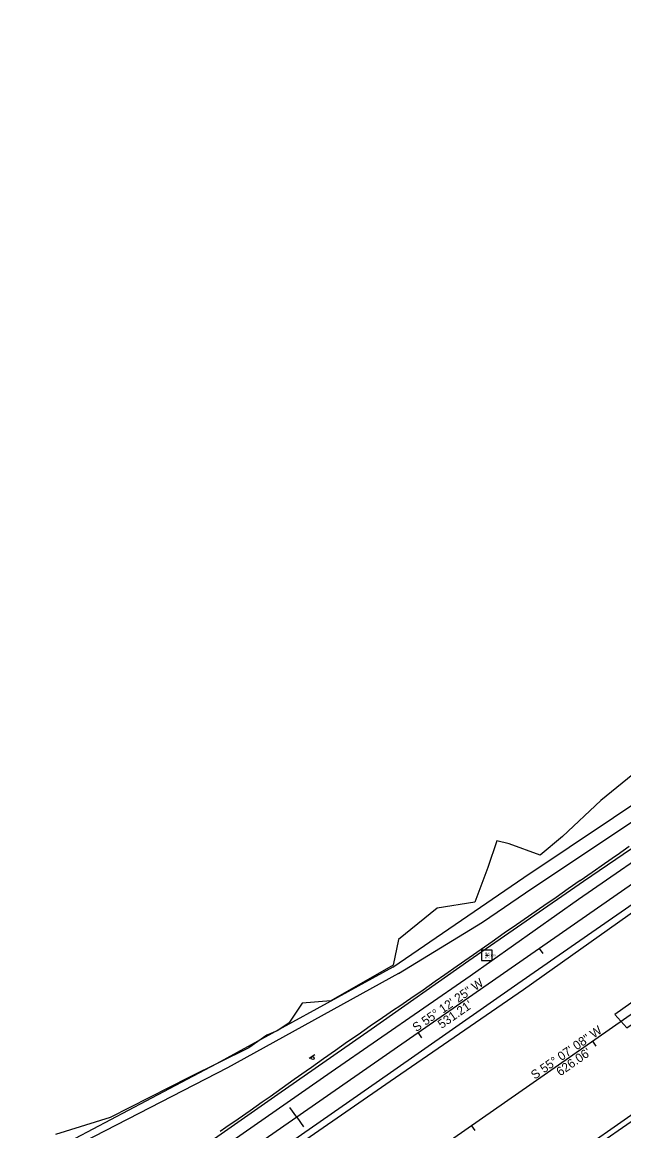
# Model space of a CAD drawing. Extents: x 1901471 to 1963503, y 756461 to 799997.
# Drawn here: x 1902497 to 1902904, y 757432 to 758182 of the extents above; entities that cross this region are included whole.
import ezdxf

# ---------------------------------------------------------------- set-up
doc = ezdxf.new("R2010")
doc.units = 0
for name, color, linetype in [('RD_DTM_BkLn1', 7, 'Continuous'), ('RD_EX_Bldg', 7, 'Continuous'), ('RD_EX_BldgApp', 7, 'Continuous'), ('RD_EX_DR_ErosCtrl', 7, 'Continuous'), ('RD_EX_Road', 7, 'Continuous'), ('RD_EX_Road_txCode', 7, 'Continuous'), ('RD_EX_VEG', 7, 'Continuous'), ('RD_HC_Cl', 7, 'Continuous'), ('RD_HC_Data', 7, 'Continuous'), ('RD_HC_Data_Tic', 7, 'Continuous'), ('RD_HC_Survey', 7, 'Continuous'), ('RD_HC_txCode', 7, 'Continuous'), ('RD_SMD_Locator', 7, 'Continuous')]:
    doc.layers.add(name, color=color, linetype=linetype)

# ---------------------------------------------------------------- blocks, each defined once
blk = doc.blocks.new('SIGN')
at = {"layer": 'RD_EX_BldgApp'}
blk.add_line((-4.5, -2), (4.5, -2), dxfattribs=at)
blk.add_circle((0, 0), 2, dxfattribs=at)

msp = doc.modelspace()

# ---------------------------------------------------------------- linework, layer by layer
at = {"layer": 'RD_DTM_BkLn1'}
for points in [[(1902874.32, 757601.2), (1902882.5, 757606.95), (1902890.67, 757612.7), (1902898.85, 757618.46), (1902899.21, 757618.71), (1902907.4, 757624.45)], [(1902874.32, 757601.2), (1902866.12, 757595.49), (1902857.91, 757589.79), (1902849.71, 757584.08), (1902841.51, 757578.37), (1902839.34, 757576.86), (1902831.13, 757571.17), (1902822.92, 757565.48), (1902814.71, 757559.79), (1902807.28, 757554.64), (1902799.11, 757548.89), (1902790.93, 757543.15), (1902782.76, 757537.4), (1902776.16, 757532.76), (1902767.92, 757527.1), (1902759.69, 757521.44), (1902751.46, 757515.78), (1902748.68, 757513.88), (1902740.46, 757508.21), (1902732.23, 757502.54), (1902724, 757496.87), (1902716.84, 757491.93), (1902708.68, 757486.17), (1902700.52, 757480.41), (1902692.37, 757474.65), (1902688.88, 757472.19), (1902680.71, 757466.43), (1902672.55, 757460.66), (1902664.39, 757454.9), (1902659.04, 757451.13), (1902650.85, 757445.41), (1902642.66, 757439.69), (1902634.47, 757433.97), (1902630.55, 757431.23)]]:
    msp.add_lwpolyline(points, dxfattribs=at)
at = {"layer": 'RD_EX_DR_ErosCtrl'}
for points in [[(1902747.46, 757542.46), (1902836.19, 757603.28), (1902927.62, 757664.43), (1903019.85, 757727.82), (1903105.99, 757786.13), (1903203.25, 757851.35), (1903242.32, 757877.29), (1903298.99, 757915.31), (1903338.66, 757941.04), (1903399.27, 757980.01), (1903462.39, 758020.38), (1903504.9, 758047.93), (1903529.93, 758066.9), (1903582.19, 758100.04), (1903632.56, 758131.91), (1903684.35, 758164.03), (1903699.94, 758182.29)], [(1902751.25, 757538.29), (1902808.08, 757572.96), (1902842.29, 757596.37), (1902919.08, 757647.57), (1902952.01, 757670.16), (1902995.77, 757699.76), (1903030.25, 757723.21), (1903111.16, 757778.54), (1903204.19, 757840.96), (1903254.44, 757875.32), (1903318.2, 757916.49), (1903382.9, 757957.81), (1903452, 758001.97), (1903511.04, 758039.98), (1903531.19, 758048.88), (1903599.19, 758091.54), (1903664.68, 758132.54), (1903699.94, 758153.56), (1903712.69, 758175.05)], [(1902747.46, 757542.46), (1902628.19, 757477.23), (1902496.57, 757407.55)], [(1902751.25, 757538.29), (1902635.44, 757474.33), (1902500.2, 757404.65)]]:
    msp.add_lwpolyline(points, dxfattribs=at)
msp.add_lwpolyline([(1903199.35, 757720.63), (1903054.59, 757619.06), (1902954.08, 757550.41), (1902897.83, 757510.56), (1902905.83, 757501.49), (1903034.86, 757590.27), (1903129.23, 757656.25), (1903191.88, 757700.1), (1903199.88, 757705.7), (1903250.13, 757740.42), (1903304.34, 757776.7), (1903375.13, 757825.43), (1903438.82, 757866.9), (1903517.32, 757917.55), (1903583.67, 757959.61), (1903576.56, 757969.98), (1903544.57, 757950.73), (1903466.96, 757900.52), (1903399.72, 757856.98), (1903308.19, 757794.62)], close=True, dxfattribs=at)
at = {"layer": 'RD_EX_Road'}
for points in [[(1902544.26, 757369.41), (1902570.72, 757387.8), (1902622.18, 757423.49), (1902669.73, 757456.61), (1902732.72, 757500.69), (1902798.95, 757547.06), (1902876.59, 757600.87), (1902935.77, 757641.26), (1902978.73, 757671.24), (1903030.53, 757707.27), (1903089.15, 757747.99), (1903161.76, 757796.94), (1903199.46, 757822.28), (1903310.27, 757894.1), (1903405, 757954.73), (1903466.2, 757993.19), (1903543.88, 758041.32), (1903647.51, 758104.6), (1903717.43, 758146.66)], [(1902549.89, 757362.97), (1902608.83, 757404.26), (1902705.74, 757471.74), (1902799.73, 757536.65), (1902873.23, 757588.57), (1902936.5, 757632.27), (1902993.18, 757671.04), (1903109.1, 757751.12), (1903199.43, 757812.56), (1903258.13, 757850.9), (1903325.96, 757895.04), (1903389.06, 757935.18), (1903464.89, 757982.87), (1903523.83, 758019.15), (1903589, 758059.44), (1903665.72, 758105.79), (1903735.62, 758147.86)], [(1902568.41, 757341.74), (1902587.99, 757355.26), (1902664.42, 757409.2), (1902745.6, 757465.34), (1902835.93, 757527.5), (1902925.89, 757591.32), (1902994.27, 757639.22), (1903088.26, 757703.77), (1903147.87, 757743.81), (1903191.75, 757773.43), (1903200.16, 757779.65), (1903243.02, 757807.06), (1903304.64, 757847.2), (1903362.69, 757886.01), (1903465.18, 757951.02), (1903571.82, 758016.63), (1903672.83, 758077.8), (1903785.09, 758144.01)], [(1902565.36, 757345.24), (1902587.93, 757360.91), (1902678.13, 757424.09), (1902745.99, 757471.23), (1902832.13, 757531.57), (1902912.99, 757587.64), (1902992.63, 757642.29), (1903093.4, 757712.18), (1903200.26, 757784.5), (1903242.13, 757812.69), (1903303.45, 757852.68), (1903394.98, 757911.48), (1903474.66, 757961.39), (1903541.6, 758003.16), (1903638.76, 758062.84), (1903731.48, 758118.38)], [(1902642.69, 757256.64), (1902673.85, 757278.35), (1902740.23, 757324.07), (1902776.75, 757349.93), (1902855.4, 757405.11), (1902924.98, 757453.9), (1903008.95, 757512.15), (1903064.67, 757550.8), (1903124.84, 757592.59), (1903162.77, 757619.44), (1903199.56, 757645.18), (1903308.36, 757720.73), (1903405.55, 757786.65), (1903520.21, 757864.13), (1903629.25, 757935.1), (1903744.21, 758008.43)], [(1902645.38, 757253.55), (1902740.71, 757320.07), (1902853.67, 757399.92), (1902941.03, 757460.46), (1903022.29, 757516.73), (1903115.34, 757581.75), (1903177.91, 757624.61), (1903200.26, 757640.46), (1903294.43, 757705.62), (1903403.47, 757780.73), (1903463.92, 757821.32), (1903530.58, 757865.32), (1903625.69, 757927.99), (1903700.66, 757976.28), (1903748.66, 758006.65)]]:
    msp.add_lwpolyline(points, dxfattribs=at)
at = {"layer": 'RD_EX_VEG'}
msp.add_lwpolyline([(1902909.89, 757673), (1902888.32, 757655.45), (1902862.24, 757631.12), (1902847.11, 757618.34), (1902826.27, 757626.11), (1902817.75, 757628.19), (1902811.68, 757610), (1902803.04, 757586.47), (1902777.46, 757582.46), (1902751.38, 757561.39), (1902747.65, 757543.88), (1902705.58, 757519.82), (1902686.16, 757518.25), (1902677.13, 757504.7), (1902669.21, 757499.55), (1902662.08, 757496.43), (1902650.04, 757487.9), (1902609.41, 757467.83), (1902556.24, 757440.74), (1902519.12, 757429.21)], dxfattribs=at)
at = {"layer": 'RD_HC_Cl'}
for p, q in [((1903005.49, 757665.55), (1902569.24, 757362.43)), ((1903124.37, 757660.86), (1902610.79, 757302.84))]:
    msp.add_line(p, q, dxfattribs=at)
at = {"layer": 'RD_HC_Data_Tic'}
for p, q in [((1902846.62, 757555.16), (1902848.9, 757551.87)), ((1902764.5, 757498.1), (1902766.78, 757494.81)), ((1902882.68, 757492.38), (1902884.97, 757489.1)), ((1902682.37, 757441.04), (1902677.81, 757447.61)), ((1902682.37, 757441.04), (1902686.94, 757434.47)), ((1902800.65, 757435.19), (1902802.93, 757431.91))]:
    msp.add_line(p, q, dxfattribs=at)
at = {"layer": 'RD_HC_Survey'}
msp.add_lwpolyline([(1902814.61, 757554.05), (1902807.54, 757554.05), (1902807.54, 757546.98), (1902814.61, 757546.98)], close=True, dxfattribs=at)
msp.add_circle((1902811.08, 757550.51), 0.5, dxfattribs=at)
at = {"layer": 'RD_SMD_Locator'}
msp.add_circle((1902811.08, 757550.51), 0.001, dxfattribs=at)

# ---------------------------------------------------------------- block references
at = {"layer": 'RD_EX_Bldg', "xscale": 0.5039370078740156, "yscale": 0.5039370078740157, "rotation": -146.88865800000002}
msp.add_blockref('SIGN', (1902693.22, 757481.04), dxfattribs=at)

# ---------------------------------------------------------------- texts
at = {"layer": 'RD_EX_Road_txCode'}
msp.add_text('401.580', height=1, dxfattribs=at).set_placement((1902812.08, 757550.01))
at = {"layer": 'RD_HC_Data'}
for s, rotation, p in [('S 55%%d 12\' 25" W', 34.793, (1902763.32, 757498.5)), ("531.21'", 34.793, (1902780.5, 757500.69)), ('S 55%%d 07\' 08" W', 34.88102, (1902843.56, 757466.32)), ("626.06'", 34.88102, (1902860.73, 757468.55))]:
    msp.add_text(s, height=6, rotation=rotation, dxfattribs=at).set_placement(p)
at = {"layer": 'RD_HC_txCode'}
for s, p in [('8018', (1902809.69, 757551.51)), ('MSC', (1902809.76, 757548.51))]:
    msp.add_text(s, height=1, dxfattribs=at).set_placement(p)

doc.saveas('drawing.dxf')
